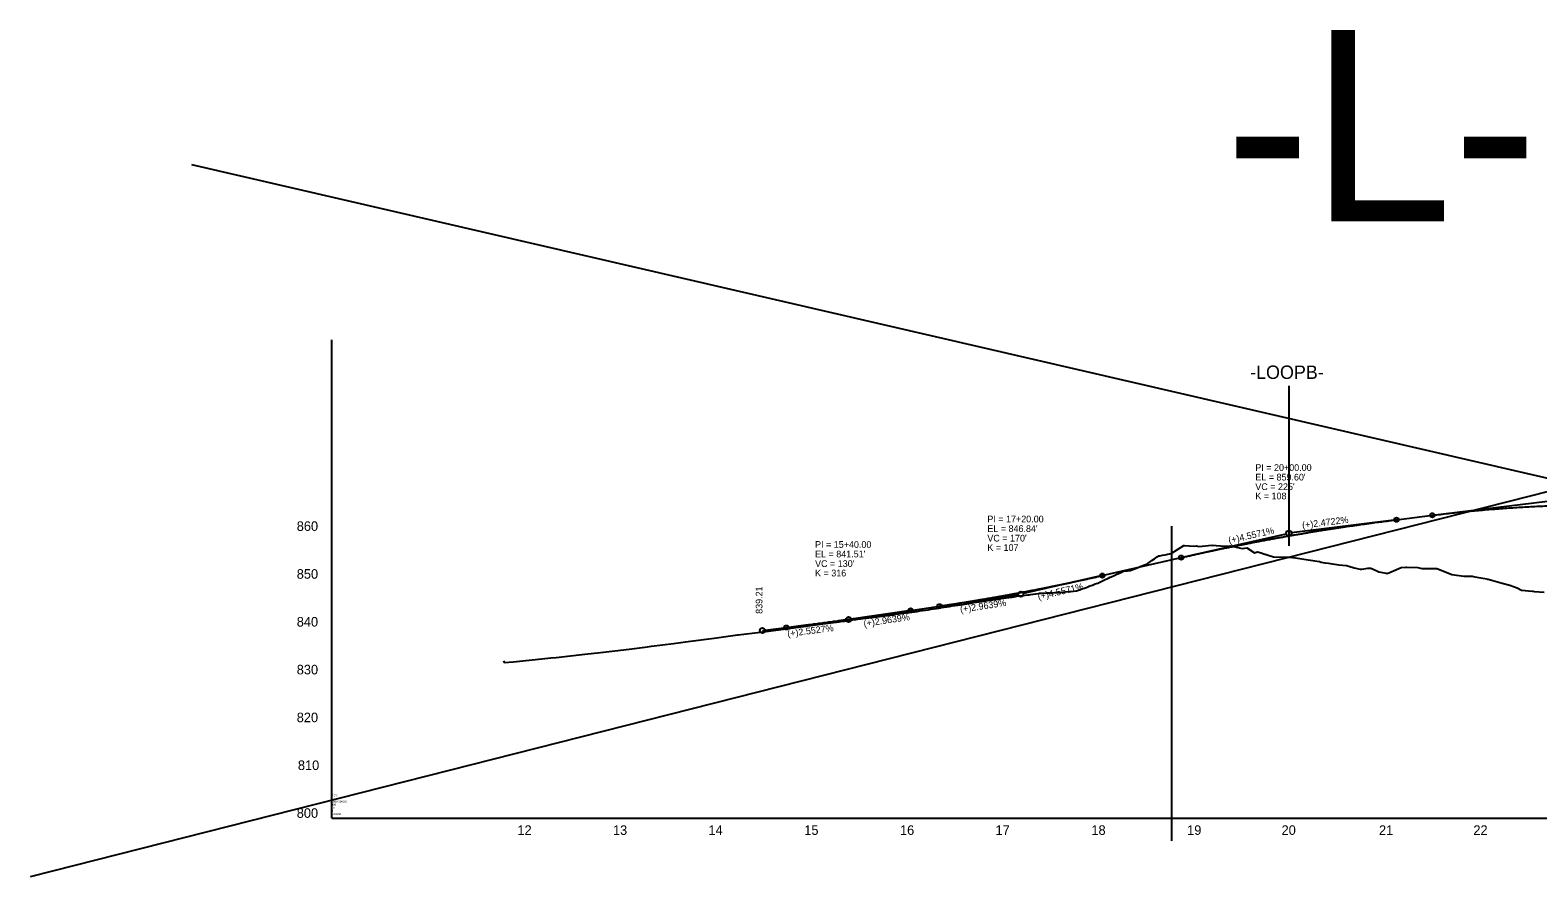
# Model space of a CAD drawing. Extents: x 570622 to 580296, y -55533 to -48575.
# Drawn here: x 573706 to 575281, y -51546 to -50661 of the extents above; entities that cross this region are included whole.
import ezdxf

# ---------------------------------------------------------------- set-up
doc = ezdxf.new("R2010")
doc.units = 0
for name, color, linetype in [('Default', 7, 'Continuous'), ('Exist Profile Cell', 7, 'Continuous'), ('Exist Vertical Profile Ground Line', 7, 'Continuous'), ('Exist Vertical Profile Horizontal Axis Label Major', 7, 'Continuous'), ('Exist Vertical Profile Vertical Axis Label', 7, 'Continuous'), ('Prop Vertical Profile Curve Label', 7, 'Continuous'), ('Prop Vertical Profile Grade', 7, 'Continuous'), ('Prop Vertical Profile Grade Label', 7, 'Continuous'), ('Prop VPI Label', 7, 'Continuous')]:
    doc.layers.add(name, color=color, linetype=linetype)

msp = doc.modelspace()

# ---------------------------------------------------------------- linework, layer by layer
at = {"layer": 'Default'}
for p, q in [((575021, -51032.8), (575021, -51199.9)), ((574898.9, -51508.3), (574898.9, -51179.6))]:
    msp.add_line(p, q, dxfattribs=at)
at = {"layer": 'Exist Profile Cell'}
for p, q in [((573874.3, -50801.3), (576976.7, -51519.5)), ((576604.4, -50810.1), (573705.9, -51546.1)), ((574021, -51484.7), (574021, -50984.7)), ((574021, -51484.7), (576617.2, -51484.7)), ((574021, -51484.7), (574021, -51484.7))]:
    msp.add_line(p, q, dxfattribs=at)
at = {"layer": 'Exist Vertical Profile Ground Line'}
for points in [[(574717.2, -51255.7), (574719.3, -51255.4), (574720, -51255.2), (574722.9, -51254.8), (574725.7, -51254.4), (574728.5, -51254), (574731.3, -51253.6), (574731.8, -51253.6), (574734.1, -51253.2), (574736.9, -51252.8), (574739.8, -51252.4), (574740.3, -51252.3), (574742.6, -51252), (574745.4, -51251.7), (574748.2, -51251.3), (574749.6, -51251.1), (574751, -51251), (574753.8, -51250.6), (574756.3, -51250.3), (574756.7, -51250.2), (574759.5, -51249.8), (574761.2, -51249.6), (574762.3, -51249.5), (574765.1, -51249.4), (574767.9, -51249.3), (574770.7, -51249.1), (574773.6, -51249), (574776.4, -51248.9), (574779.2, -51248.8), (574782, -51248.8), (574782.4, -51248.7), (574784.8, -51248.5), (574787.6, -51248.2), (574790.5, -51247.9), (574793.3, -51247.6), (574796.1, -51247.3), (574799.1, -51247.1), (574802.3, -51246.1), (574802.6, -51245.9), (574803.3, -51245.6), (574804.6, -51245.1), (574807.4, -51244.1), (574810.2, -51243.1), (574813, -51242), (574815.8, -51241), (574818.6, -51239.9), (574821.5, -51238.9), (574822.9, -51238.3), (574824.3, -51237.7), (574827.1, -51236.3), (574829.9, -51235), (574832.7, -51233.7), (574834.2, -51232.9), (574835.5, -51232.3), (574838.4, -51231.1), (574841.2, -51229.8), (574844, -51228.5), (574846.8, -51227.2), (574848.8, -51226.2), (574849.6, -51226.2), (574852.4, -51226.1), (574855.3, -51225.8), (574858.1, -51224.7), (574860.9, -51223.6), (574863.7, -51222.5), (574866.5, -51221.3), (574867, -51221.1), (574869.3, -51220.2), (574872.2, -51219.1), (574873.6, -51218.5), (574875, -51217.5), (574877.8, -51215.5), (574880.6, -51213.5), (574883.4, -51211.5), (574884.1, -51211), (574885.1, -51210.6), (574886.2, -51210.4), (574889.1, -51209.8), (574891.9, -51209.3), (574894.7, -51208.7), (574898.1, -51208), (574911.2, -51199.6), (574911.8, -51199.5), (574921.7, -51200.3), (574924, -51200.1), (574926.9, -51200.7), (574940.6, -51199.4), (574941, -51199.4), (574953.7, -51200.4), (574955.3, -51200.2), (574959.8, -51200), (574972.1, -51202.7), (574977, -51202.2), (574985.1, -51207.3), (574988.4, -51206.3), (574992.1, -51207.3), (574993.7, -51208.1), (575005, -51211.6), (575021.2, -51211.8), (575027.9, -51212.4), (575041.3, -51214.7)], [(575041.3, -51214.7), (575053, -51216.4), (575054.8, -51217), (575058.6, -51217.7), (575062.5, -51218.2), (575073.1, -51219.9), (575081.4, -51220.5), (575083.6, -51221.4), (575089.4, -51222.9), (575095.6, -51224.3), (575097.4, -51224.4), (575103.4, -51223.2), (575106.5, -51223.5), (575112.4, -51225.9), (575115, -51227.3), (575122.8, -51228.7), (575123.8, -51228.9), (575128, -51227.1), (575138.2, -51222.5), (575143.3, -51222.3), (575144.3, -51222.3), (575155.9, -51222.8), (575159.9, -51223.7), (575168, -51223.8), (575175.6, -51223.7), (575180.1, -51225.6), (575191.2, -51230), (575203.8, -51231.7), (575212.6, -51231.8), (575215.4, -51232.3), (575225.7, -51234.1), (575227.7, -51234.5), (575228.3, -51234.7), (575229.4, -51235), (575244, -51239.2), (575251.8, -51241.1), (575259.6, -51244), (575264, -51246.2), (575275.3, -51247.4), (575275.9, -51247.5), (575277.6, -51247.7), (575287.9, -51248.6)], [(574200.6, -51320.4), (574201.3, -51322.1), (574210.6, -51321.2), (574240.4, -51318.2), (574249.8, -51317.2), (574255.4, -51316.7), (574285.5, -51313.3), (574301.9, -51311.5), (574331.8, -51307.9), (574348.1, -51305.9), (574355, -51305), (574378.2, -51302.1), (574395.8, -51299.8), (574420.6, -51296.5), (574445.1, -51293.2), (574445.6, -51293.1), (574469, -51290.1), (574469.4, -51290.1), (574493.1, -51287.1), (574516.4, -51284.1), (574531.3, -51282), (574534.1, -51281.6), (574536.9, -51281.2), (574539.1, -51280.9), (574539.7, -51280.8), (574542.6, -51280.4), (574545.4, -51280), (574548.2, -51279.7), (574551, -51279.3), (574553.8, -51278.9), (574556.6, -51278.6), (574559.5, -51278.2), (574562.3, -51277.8), (574565.1, -51277.4), (574567.9, -51277.1), (574568.4, -51277), (574570.7, -51276.7), (574573.5, -51276.3), (574576.4, -51276), (574579.2, -51275.6), (574582, -51275.3), (574584.8, -51274.9), (574585.3, -51274.8), (574587.6, -51274.5), (574590.5, -51274.2), (574593.3, -51273.8), (574596.1, -51273.4), (574598.9, -51273.1), (574601.7, -51272.7), (574604.5, -51272.3), (574606, -51272.1), (574607.4, -51272), (574608.2, -51271.8), (574610.2, -51271.6), (574613, -51271.2), (574615.8, -51270.8), (574618.6, -51270.4), (574621.4, -51270), (574624.3, -51269.6), (574626.7, -51269.3), (574627.1, -51269.3), (574629.9, -51268.9), (574631.2, -51268.7), (574632.7, -51268.5), (574635.5, -51268.1), (574638.3, -51267.6), (574641.2, -51267.2), (574644, -51266.8), (574646.5, -51266.4), (574646.8, -51266.3), (574649.6, -51265.9), (574652.4, -51265.5), (574652.9, -51265.4), (574655.2, -51265.1), (574658.1, -51264.6), (574660.9, -51264.2), (574663.7, -51263.8), (574665.5, -51263.5), (574666.5, -51263.3), (574669.3, -51262.9), (574672.1, -51262.5), (574674.5, -51262.1), (574675, -51262), (574677.8, -51261.6), (574680.6, -51261.2), (574683.4, -51260.7), (574684.4, -51260.6), (574686.2, -51260.3), (574689, -51259.9), (574691.9, -51259.4), (574694.7, -51259), (574696.9, -51258.7), (574697.5, -51258.6), (574700.3, -51258.2), (574703.1, -51257.7), (574706, -51257.3), (574708.8, -51256.9), (574711.6, -51256.5), (574714.4, -51256.1), (574716, -51255.8), (574717.2, -51255.7)]]:
    msp.add_lwpolyline(points, dxfattribs=at)
at = {"layer": 'Prop Vertical Profile Curve Label'}
for centre in [(575133.5, -51172.7), (575171, -51168.1), (574908.5, -51212.3), (574826, -51231.1), (574626, -51267.5), (574656, -51263.1), (574496, -51285.4)]:
    msp.add_circle(centre, 2.25, dxfattribs=at)
at = {"layer": 'Prop Vertical Profile Grade'}
for p, q in [((575133.5, -51172.7), (575171, -51168.1)), ((574826, -51231.1), (574908.5, -51212.3)), ((574626, -51267.5), (574656, -51263.1)), ((574471, -51288.6), (574496, -51285.4))]:
    msp.add_line(p, q, dxfattribs=at)
for points in [[(575171, -51168.1), (575179.4, -51167.1), (575187.8, -51166.1), (575196.2, -51165.2), (575204.6, -51164.3), (575213, -51163.5), (575221.4, -51162.8), (575229.8, -51162), (575238.2, -51161.4), (575246.6, -51160.7), (575255, -51160.2), (575263.4, -51159.6), (575271.8, -51159.1), (575280.2, -51158.7), (575288.6, -51158.3), (575297, -51158), (575305.4, -51157.7), (575313.8, -51157.5), (575322.2, -51157.3), (575330.6, -51157.1), (575339, -51157), (575347.4, -51157), (575355.8, -51157), (575364.2, -51157), (575372.6, -51157.1), (575381, -51157.3), (575389.4, -51157.5), (575397.8, -51157.7), (575406.2, -51158), (575414.6, -51158.4), (575423, -51158.8), (575431.4, -51159.2), (575439.8, -51159.7), (575448.2, -51160.2), (575456.6, -51160.8), (575465, -51161.4), (575473.4, -51162.1), (575481.8, -51162.9), (575490.2, -51163.6), (575498.6, -51164.5), (575507, -51165.3), (575515.4, -51166.3), (575523.8, -51167.2), (575532.2, -51168.3), (575540.6, -51169.3), (575549, -51170.4), (575557.4, -51171.6), (575565.8, -51172.8), (575574.2, -51174.1), (575582.6, -51175.4), (575591, -51176.8)], [(574908.5, -51212.3), (574913, -51211.3), (574917.5, -51210.3), (574922, -51209.3), (574926.5, -51208.3), (574931, -51207.3), (574935.5, -51206.3), (574940, -51205.3), (574944.5, -51204.4), (574949, -51203.4), (574953.5, -51202.5), (574958, -51201.6), (574962.5, -51200.7), (574967, -51199.8), (574971.5, -51198.9), (574976, -51198), (574980.5, -51197.1), (574985, -51196.2), (574989.5, -51195.4), (574994, -51194.5), (574998.5, -51193.7), (575003, -51192.8), (575007.5, -51192), (575012, -51191.2), (575016.5, -51190.4), (575021, -51189.6), (575025.5, -51188.8), (575030, -51188), (575034.5, -51187.3), (575039, -51186.5), (575043.5, -51185.7), (575048, -51185), (575052.5, -51184.3), (575057, -51183.6), (575061.5, -51182.8), (575066, -51182.1), (575070.5, -51181.5), (575075, -51180.8), (575079.5, -51180.1), (575084, -51179.4), (575088.5, -51178.8), (575093, -51178.1), (575097.5, -51177.5), (575102, -51176.9), (575106.5, -51176.3), (575111, -51175.6), (575115.5, -51175), (575120, -51174.5), (575124.5, -51173.9), (575129, -51173.3), (575133.5, -51172.7)], [(574656, -51263.1), (574659.4, -51262.5), (574662.8, -51262), (574666.2, -51261.5), (574669.6, -51261), (574673, -51260.5), (574676.4, -51259.9), (574679.8, -51259.4), (574683.2, -51258.8), (574686.6, -51258.3), (574690, -51257.7), (574693.4, -51257.2), (574696.8, -51256.6), (574700.2, -51256), (574703.6, -51255.5), (574707, -51254.9), (574710.4, -51254.3), (574713.8, -51253.7), (574717.2, -51253.1), (574720.6, -51252.5), (574724, -51251.9), (574727.4, -51251.3), (574730.8, -51250.7), (574734.2, -51250), (574737.6, -51249.4), (574741, -51248.8), (574744.4, -51248.1), (574747.8, -51247.5), (574751.2, -51246.8), (574754.6, -51246.2), (574758, -51245.5), (574761.4, -51244.8), (574764.8, -51244.2), (574768.2, -51243.5), (574771.6, -51242.8), (574775, -51242.1), (574778.4, -51241.4), (574781.8, -51240.7), (574785.2, -51240), (574788.6, -51239.3), (574792, -51238.6), (574795.4, -51237.8), (574798.8, -51237.1), (574802.2, -51236.4), (574805.6, -51235.6), (574809, -51234.9), (574812.4, -51234.1), (574815.8, -51233.4), (574819.2, -51232.6), (574822.6, -51231.9), (574826, -51231.1)], [(574496, -51285.4), (574498.6, -51285.1), (574501.2, -51284.8), (574503.8, -51284.4), (574506.4, -51284.1), (574509, -51283.8), (574511.6, -51283.4), (574514.2, -51283.1), (574516.8, -51282.7), (574519.4, -51282.4), (574522, -51282.1), (574524.6, -51281.7), (574527.2, -51281.4), (574529.8, -51281), (574532.4, -51280.7), (574535, -51280.3), (574537.6, -51280), (574540.2, -51279.6), (574542.8, -51279.3), (574545.4, -51278.9), (574548, -51278.6), (574550.6, -51278.2), (574553.2, -51277.9), (574555.8, -51277.5), (574558.4, -51277.2), (574561, -51276.8), (574563.6, -51276.4), (574566.2, -51276.1), (574568.8, -51275.7), (574571.4, -51275.4), (574574, -51275), (574576.6, -51274.6), (574579.2, -51274.3), (574581.8, -51273.9), (574584.4, -51273.5), (574587, -51273.2), (574589.6, -51272.8), (574592.2, -51272.4), (574594.8, -51272), (574597.4, -51271.7), (574600, -51271.3), (574602.6, -51270.9), (574605.2, -51270.5), (574607.8, -51270.2), (574610.4, -51269.8), (574613, -51269.4), (574615.6, -51269), (574618.2, -51268.6), (574620.8, -51268.3), (574623.4, -51267.9), (574626, -51267.5)]]:
    msp.add_spline(points, degree=3, dxfattribs=at)
at = {"layer": 'Prop VPI Label'}
for p, q in [((575171, -51168.1), (575378.3, -51142.5)), ((575133.5, -51172.7), (575023.7, -51186.3)), ((574908.5, -51212.3), (575018.3, -51187.3)), ((574826, -51231.1), (574743.7, -51249.8)), ((574656, -51263.1), (574738.3, -51250.9)), ((574626, -51267.5), (574563.7, -51276.7)), ((574496, -51285.4), (574558.3, -51277.5))]:
    msp.add_line(p, q, dxfattribs=at)
for centre in [(575021, -51186.7), (574741, -51250.5), (574561, -51277.1), (574471, -51288.6)]:
    msp.add_circle(centre, 2.75, dxfattribs=at)

# ---------------------------------------------------------------- texts
at = {"layer": 'Default'}
msp.add_text('-L-', height=200, dxfattribs=at).set_placement((574954.3, -50860.9))
at = {"layer": 'Exist Profile Cell'}
for s, height, p in [('-LOOPB-', 14, (574980.5, -51025.5)), ('RDY', 2, (574021, -51461.9)), ('L', 2, (574021, -51465.2)), ('800', 2, (574021, -51471.7)), ('2', 2, (574021, -51478.2)), ('1000.000000', 2, (574021, -51468.4)), ('10', 2, (574021, -51474.9)), ('NOGAP', 2, (574021, -51481.4))]:
    msp.add_text(s, height=height, dxfattribs=at).set_placement(p)
at = {"layer": 'Exist Vertical Profile Horizontal Axis Label Major'}
for s, p in [('12', (574215, -51502.2)), ('13', (574314.8, -51502.2)), ('14', (574414.6, -51502.2)), ('15', (574514.7, -51502.2)), ('16', (574614.7, -51502.2)), ('17', (574714.5, -51502.2)), ('18', (574814.7, -51502.2)), ('19', (574914.7, -51502.2)), ('20', (575013.4, -51502.2)), ('21', (575115.2, -51502.2)), ('22', (575213.8, -51502.2))]:
    msp.add_text(s, height=10, dxfattribs=at).set_placement(p)
at = {"layer": 'Exist Vertical Profile Vertical Axis Label'}
for s, p in [('860', (573984.4, -51184.4)), ('850', (573984.4, -51234.4)), ('840', (573984.4, -51284.4)), ('830', (573984.4, -51334.4)), ('820', (573984.4, -51384.4)), ('810', (573985.6, -51434.4)), ('800', (573984.4, -51484.4))]:
    msp.add_text(s, height=10, dxfattribs=at).set_placement(p)
at = {"layer": 'Prop Vertical Profile Curve Label'}
for s, p in [("VC = 225'", (574986, -51141.7)), ('K = 108', (574986, -51151.4)), ("VC = 170'", (574706, -51195.5)), ('K = 107', (574706, -51205.3)), ("VC = 130'", (574526, -51222.1)), ('K = 316', (574526, -51232))]:
    msp.add_text(s, height=7, dxfattribs=at).set_placement(p)
at = {"layer": 'Prop Vertical Profile Grade Label'}
for s, rotation, p in [('(+)4.5571%', 12.8361, (574958.7, -51197.8)), ('(+)2.4722%', 7.0466, (575035.3, -51181.9)), ('(+)4.5571%', 12.8361, (574759.5, -51256.5)), ('(+)2.9639%', 8.4296, (574678, -51269.9)), ('(+)2.9639%', 8.4296, (574577.2, -51284.8)), ('(+)2.5527%', 7.2735, (574497.4, -51295.3))]:
    msp.add_text(s, height=7, rotation=rotation, dxfattribs=at).set_placement(p)
at = {"layer": 'Prop VPI Label'}
for s, p in [('PI = 20+00.00', (574986, -51121.7)), ("EL = 859.60'", (574986, -51131.7)), ('PI = 17+20.00', (574706, -51175.5)), ("EL = 846.84'", (574706, -51185.5)), ('PI = 15+40.00', (574526, -51202.1)), ("EL = 841.51'", (574526, -51212.1))]:
    msp.add_text(s, height=7, dxfattribs=at).set_placement(p)
msp.add_text('839.21', height=7, rotation=90, dxfattribs=at).set_placement((574471, -51271.1))

doc.saveas('drawing.dxf')
